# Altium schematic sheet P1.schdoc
size 297 x 209 mm; Symbol: Drawing-Symbol_A4; @Project Name: Macropad; @Page Count: 1; @Update Date: 2026-10-06; @Create Date: 2026-10-06; @Schematic Name: Schematic1; @Page No: 1; @Page Name: P1; Company: EasyEDA.com; Version: V1.0; Page Size: A4; Device: Drawing-Symbol_A4; @Create Time: 18:20:39; @Update Time: 18:20:39; Border: 1; Width: 1170; Height: 825; Region Start: 1; X Region Count: 6; Y Region Count: 4; Blade Width: 10; Title Block Position: 3; @Board Name: Board1
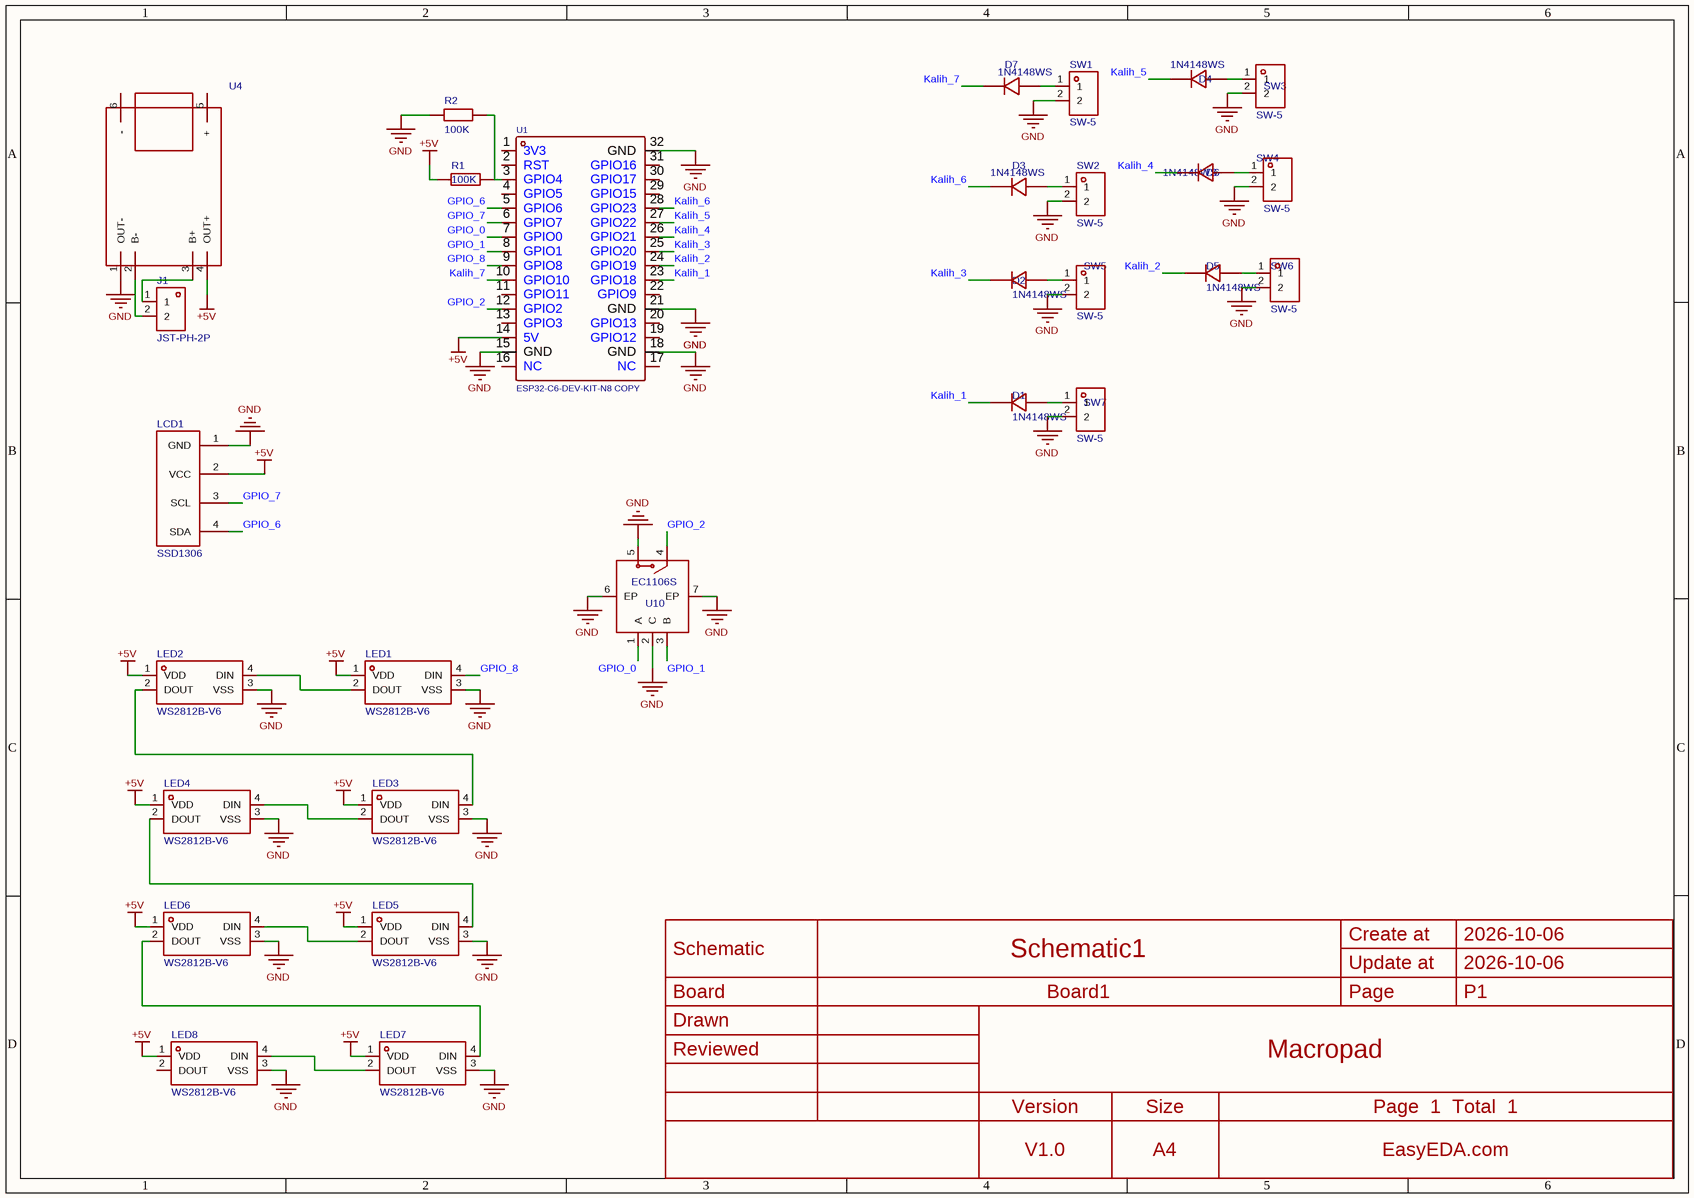
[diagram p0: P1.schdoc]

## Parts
D1  1N4148WS  [SOD-323_L1.8-W1.3-LS2.5-RD]
D2  1N4148WS  [SOD-323_L1.8-W1.3-LS2.5-RD]
D3  1N4148WS  [SOD-323_L1.8-W1.3-LS2.5-RD]
D4  1N4148WS  [SOD-323_L1.8-W1.3-LS2.5-RD]
D5  1N4148WS  [SOD-323_L1.8-W1.3-LS2.5-RD]
D6  1N4148WS  [SOD-323_L1.8-W1.3-LS2.5-RD]
D7  1N4148WS  [SOD-323_L1.8-W1.3-LS2.5-RD]
J1  JST-PH-2P  [JST-PH-2P]
LCD1  SSD1306  [SSD1306]
LED1  WS2812B-V6  [LED-SMD_4P-L5.0-W5.0-TL-A]
LED2  WS2812B-V6  [LED-SMD_4P-L5.0-W5.0-TL-A]
LED3  WS2812B-V6  [LED-SMD_4P-L5.0-W5.0-TL-A]
LED4  WS2812B-V6  [LED-SMD_4P-L5.0-W5.0-TL-A]
LED5  WS2812B-V6  [LED-SMD_4P-L5.0-W5.0-TL-A]
LED6  WS2812B-V6  [LED-SMD_4P-L5.0-W5.0-TL-A]
LED7  WS2812B-V6  [LED-SMD_4P-L5.0-W5.0-TL-A]
LED8  WS2812B-V6  [LED-SMD_4P-L5.0-W5.0-TL-A]
R1  100K  [R0805]
R2  100K  [R0805]
SW1  SW-5  [SW-SMD_KAILH-SOCKET_C9900019772]
SW2  SW-5  [SW-SMD_KAILH-SOCKET_C9900019772]
SW3  SW-5  [SW-SMD_KAILH-SOCKET_C9900019772]
SW4  SW-5  [SW-SMD_KAILH-SOCKET_C9900019772]
SW5  SW-5  [SW-SMD_KAILH-SOCKET_C9900019772]
SW6  SW-5  [SW-SMD_KAILH-SOCKET_C9900019772]
SW7  SW-5  [SW-SMD_KAILH-SOCKET_C9900019772]
U1  ESP32-C6-DEV-KIT-N8 COPY  [COMM-SMD_L55.0-W25.4_ESP32-C6-DEV-KIT-N8]
U4  (no value)  [TP4056 TYPE-C MODULE, 18650 1A LIPO BATTERY CHARGING BOARD]
U10  EC1106S  [SW-SMD_EC1106S]

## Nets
+5V: LCD1.2(VCC) LED1.1(VDD) LED2.1(VDD) LED3.1(VDD) LED4.1(VDD) LED5.1(VDD) LED6.1(VDD) LED7.1(VDD) LED8.1(VDD) R1.1 U1.14(5V) U4.4(OUT+)
GND: LCD1.1(GND) LED1.3(VSS) LED2.3(VSS) LED3.3(VSS) LED4.3(VSS) LED5.3(VSS) LED6.3(VSS) LED7.3(VSS) LED8.3(VSS) R2.1 SW1.2 SW2.2 SW3.2 SW4.2 SW5.2 SW6.2 SW7.2 U1.15(GND) U1.18(GND) U1.21(GND) U1.32(GND) U4.1(OUT-) U10.2(C) U10.5(D) U10.6(EP) U10.7(EP)
GPIO_0: U1.7(GPIO0) U10.1(A)
GPIO_1: U1.8(GPIO1) U10.3(B)
GPIO_2: U1.12(GPIO2) U10.4(E)
GPIO_6: LCD1.4(SDA) U1.5(GPIO6)
GPIO_7: LCD1.3(SCL) U1.6(GPIO7)
GPIO_8: LED1.4(DIN) U1.9(GPIO8)
Kalih_1: D1.1(K) U1.23(GPIO18)
Kalih_2: D5.1(K) U1.24(GPIO19)
Kalih_3: D2.1(K) U1.25(GPIO20)
Kalih_4: D6.1(K) U1.26(GPIO21)
Kalih_5: D4.1(K) U1.27(GPIO22)
Kalih_6: D3.1(K) U1.28(GPIO23)
Kalih_7: D7.1(K) U1.10(GPIO10)
NetD1_2: D1.2(A) SW7.1
NetD2_2: D2.2(A) SW5.1
NetD3_2: D3.2(A) SW2.1
NetD4_2: D4.2(A) SW3.1
NetD5_2: D5.2(A) SW6.1
NetD6_2: D6.2(A) SW4.1
NetD7_2: D7.2(A) SW1.1
NetJ1_1: J1.1 U4.3(B+)
NetJ1_2: J1.2 U4.2(B-)
NetLED1_2: LED1.2(DOUT) LED2.4(DIN)
NetLED2_2: LED2.2(DOUT) LED3.4(DIN)
NetLED3_2: LED3.2(DOUT) LED4.4(DIN)
NetLED4_2: LED4.2(DOUT) LED5.4(DIN)
NetLED5_2: LED5.2(DOUT) LED6.4(DIN)
NetLED6_2: LED6.2(DOUT) LED7.4(DIN)
NetLED7_2: LED7.2(DOUT) LED8.4(DIN)
NetR1_2: R1.2 R2.2 U1.3(GPIO4)

Not connected (* = marked no-connect by the designer): LED8 2(DOUT); U1 1(3V3) 2(RST) 4(GPIO5) 11(GPIO11) 13(GPIO3) 16(NC) 17(NC) 19(GPIO12) 20(GPIO13) 22(GPIO9) 29(GPIO15) 30(GPIO17) 31(GPIO16); U4 5(+) 6(-)

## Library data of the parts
D1-D7 = 1N4148WS_C2128: Diode Configuration:Standalone Pd - Power Dissipation:200mW Current - Rectified:150mA Voltage - DC Reverse(Vr):100V Voltage - Forward(Vf@If):1.25V@150mA Non-Repetitive Peak Forward Surge Current:2A Reverse Leakage Current (Ir):1uA@75V Reverse Recovery Tim; Manufacturer: CJ(江苏长电/长晶); Symbol: 1N4148WS T4; AddInBom: yes; ModelId: 533ebfb2f206414f9035ed0ccba1097d0819f05c4eef4c71ace90d822a990e87; ModelTransform: 104.3305,51.181,0,0,0,0,0,-0.004,0; Pd - Power Dissipation: 200mW; Current - Rectified: 150mA; Voltage - DC Reverse(Vr): 100V; Non-Repetitive Peak Forward Surge Current: 2A; Reverse Recovery Time (trr): 4ns
J1 = JST-PH-2P: ConvertToPcb: yes
LCD1 = SSD1306: ConvertToPcb: yes
LED1-LED8 = WS2812B-V6: Lamp Holder Type:5.0mm x 5.0mm square LED Illumination Color:Red, green, blue Voltage - Forward(Vf):- Voltage - Forward(Vf):- Power(Watts):- Forward Current:- Wavelength - Dominant:465nm~475nm；620nm~630nm；515nm~525nm Wavelength - Dominant:465nm~475nm；620n; Manufacturer: worldsemi; AddInBom: yes; Luminous Intensity: 200mcd~300mcd；600mcd~1cd；300mcd~500mcd
R1 R2 = Res_0805: Symbol: Res; 3D Model: b83c7c5430874b8eb2319a65d94334290819f05c4eef4c71ace90d822a990e87; 3D Model Transform: 78.74,51.181,0,0,0,0,0,-0.0005,0; ConvertToPcb: yes; ModelName: R0805_L2.0-W1.3-H0.6
SW1-SW7 = SW-5: AddInBom: yes; ModelId: 26b5b8c4759f4baeb5c99d30d537ad970819f05c4eef4c71ace90d822a990e87; ModelTransform: 559.054,240.9444,0,0,0,0,0,-4.016,-47.244
U1 = ESP32-C6-DEV-KIT-N8 COPY: Manufacturer: null
U4 = TP4056 type-C module, 18650 1A Lipo Battery Charging Board: AddInBom: yes
U10 = EC1106S: AddInBom: yes; ModelId: beedc2e67ac74d2e8213a1c22d51143e0819f05c4eef4c71ace90d822a990e87; ModelTransform: 590.55,610.235,0,0,0,0,0,0,-23.622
